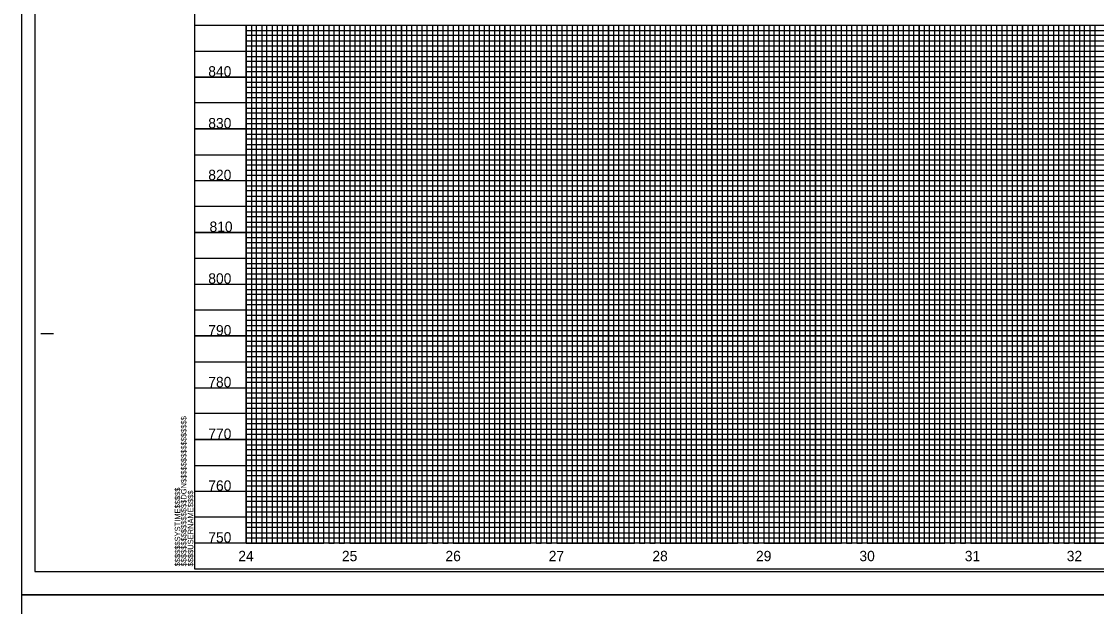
# Model space of a CAD drawing. Extents: x 1755181 to 1757273, y 729911 to 735411.
# Drawn here: x 1755181 to 1756219, y 734300 to 734864 of the extents above; entities that cross this region are included whole.
import ezdxf

# ---------------------------------------------------------------- set-up
doc = ezdxf.new("R2010")
doc.units = 0
for name, color, linetype in [('Exist Vertical Profile Horizontal Axis Label Major', 7, 'Continuous'), ('Exist Vertical Profile Vertical Axis Label', 7, 'Continuous'), ('Scratch_Level_3', 7, 'Continuous'), ('Sheet Cutting Line CELL', 7, 'Continuous'), ('Sheet DOT Grid CELL', 7, 'Continuous'), ('Sheet Plot Border Inside CELL', 7, 'Continuous'), ('Sheet Plot Border Outside CELL', 7, 'Continuous'), ('Sheet Profile CELL', 7, 'Continuous'), ('Sheet Profile Grid Major CELL', 7, 'Continuous'), ('Sheet Profile Grid Middle CELL', 7, 'Continuous'), ('Sheet Profile Grid Minor CELL', 7, 'Continuous')]:
    doc.layers.add(name, color=color, linetype=linetype)

msp = doc.modelspace()

# ---------------------------------------------------------------- linework, layer by layer
at = {"layer": 'Scratch_Level_3'}
msp.add_lwpolyline([(1755397.7, 734860.8), (1756797.7, 734860.8), (1756797.7, 734360.8), (1755397.7, 734360.8)], close=True, dxfattribs=at)
at = {"layer": 'Sheet Cutting Line CELL'}
for p, q in [((1755180.7, 735410.8), (1755180.7, 734310.8)), ((1755180.7, 734310.8), (1756864.7, 734310.8)), ((1755180.7, 734310.8), (1755180.7, 733210.8))]:
    msp.add_line(p, q, dxfattribs=at)
at = {"layer": 'Sheet DOT Grid CELL'}
for p, q in [((1755347.7, 734860.8), (1756847.6, 734860.8)), ((1755397.7, 734860.8), (1755397.7, 734360.8)), ((1755447.7, 734860.8), (1755447.7, 734360.8)), ((1755497.7, 734860.8), (1755497.7, 734360.8)), ((1755547.7, 734860.8), (1755547.7, 734360.8)), ((1755597.7, 734860.8), (1755597.7, 734360.8)), ((1755647.7, 734860.8), (1755647.7, 734360.8)), ((1755697.7, 734860.8), (1755697.7, 734360.8)), ((1755747.7, 734860.8), (1755747.7, 734360.8)), ((1755797.7, 734860.8), (1755797.7, 734360.8)), ((1755847.7, 734860.8), (1755847.7, 734360.8)), ((1755897.7, 734860.8), (1755897.7, 734360.8)), ((1755947.7, 734860.8), (1755947.7, 734360.8)), ((1755997.7, 734860.8), (1755997.7, 734360.8)), ((1756047.7, 734860.8), (1756047.7, 734360.8)), ((1756097.7, 734860.8), (1756097.7, 734360.8)), ((1756147.7, 734860.8), (1756147.7, 734360.8)), ((1756197.7, 734860.8), (1756197.7, 734360.8)), ((1755347.7, 734810.8), (1756847.6, 734810.8)), ((1755347.7, 734760.8), (1756847.6, 734760.8)), ((1755347.7, 734710.8), (1756847.6, 734710.8)), ((1755347.7, 734660.8), (1756847.6, 734660.8)), ((1755347.7, 734610.8), (1756847.6, 734610.8)), ((1755347.7, 734560.8), (1756847.6, 734560.8)), ((1755347.7, 734510.8), (1756847.6, 734510.8)), ((1755347.7, 734460.8), (1756847.6, 734460.8)), ((1755347.7, 734410.8), (1756847.6, 734410.8))]:
    msp.add_line(p, q, dxfattribs=at)
at = {"layer": 'Sheet Plot Border Inside CELL'}
msp.add_lwpolyline([(1755193.7, 734333.2), (1756860.2, 734333.2), (1756860.2, 735388.3), (1755193.7, 735388.3)], close=True, dxfattribs=at)
at = {"layer": 'Sheet Plot Border Outside CELL'}
for points in [[(1755180.7, 734310.8), (1756864.7, 734310.8), (1756864.7, 735410.8), (1755180.7, 735410.8)], [(1755180.7, 733210.8), (1756864.7, 733210.8), (1756864.7, 734310.8), (1755180.7, 734310.8)]]:
    msp.add_lwpolyline(points, close=True, dxfattribs=at)
at = {"layer": 'Sheet Profile CELL'}
for p, q in [((1755347.7, 734860.8), (1756847.7, 734860.8)), ((1755199.2, 734563.3), (1755211.7, 734563.3)), ((1756847.7, 734360.8), (1755347.7, 734360.8)), ((1755347.7, 734335.8), (1756847.7, 734335.8)), ((1755347.7, 734335.8), (1755347.7, 734335.8))]:
    msp.add_line(p, q, dxfattribs=at)
msp.add_lwpolyline([(1756847.7, 735385.8), (1755347.7, 735385.8), (1755347.7, 734335.8), (1756847.7, 734335.8)], close=True, dxfattribs=at)
msp.add_lwpolyline([(1755385.2, 734335.8), (1755385.2, 734335.8)], dxfattribs=at)
at = {"layer": 'Sheet Profile Grid Major CELL'}
for p, q in [((1755847.7, 734860.8), (1755897.7, 734860.8)), ((1755947.7, 734860.8), (1755997.7, 734860.8)), ((1756047.7, 734860.8), (1756097.7, 734860.8)), ((1756147.7, 734860.8), (1756197.7, 734860.8)), ((1755347.7, 734361.1), (1755347.7, 734361.1))]:
    msp.add_line(p, q, dxfattribs=at)
for points in [[(1755397.7, 734860.8), (1755397.7, 734360.8), (1755447.7, 734360.8), (1755447.7, 734860.8), (1755497.7, 734860.8), (1755497.7, 734360.8), (1755547.7, 734360.8), (1755547.7, 734860.8), (1755597.7, 734860.8), (1755597.7, 734360.8), (1755647.7, 734360.8), (1755647.7, 734860.8), (1755697.7, 734860.8), (1755697.7, 734360.8), (1755747.7, 734360.8), (1755747.7, 734860.8), (1755797.7, 734860.8), (1755797.7, 734360.8), (1755847.7, 734360.8), (1755847.7, 734860.8), (1755897.7, 734860.8), (1755897.7, 734360.8), (1755947.7, 734360.8), (1755947.7, 734860.8), (1755997.7, 734860.8), (1755997.7, 734360.8), (1756047.7, 734360.8), (1756047.7, 734860.8), (1756097.7, 734860.8), (1756097.7, 734360.8), (1756147.7, 734360.8), (1756147.7, 734860.8), (1756197.7, 734860.8), (1756197.7, 734360.8), (1756247.7, 734360.8)], [(1756847.7, 734810.8), (1755347.7, 734810.8)], [(1756847.7, 734760.8), (1755347.7, 734760.8), (1755347.7, 734710.8), (1756847.7, 734710.8)], [(1756847.7, 734660.8), (1755347.7, 734660.8), (1755347.7, 734610.8), (1756847.7, 734610.8)], [(1756847.7, 734560.8), (1755347.7, 734560.8), (1755347.7, 734510.8), (1756847.7, 734510.8)], [(1756847.7, 734460.8), (1755347.7, 734460.8), (1755347.7, 734460.8), (1755347.7, 734410.8), (1756847.7, 734410.8)], [(1756847.7, 734360.8), (1755347.7, 734360.8)]]:
    msp.add_lwpolyline(points, dxfattribs=at)
at = {"layer": 'Sheet Profile Grid Middle CELL'}
for points in [[(1755372.7, 734860.8), (1755422.7, 734860.8), (1755422.7, 734360.8), (1755472.7, 734360.8), (1755472.7, 734860.8), (1755522.7, 734860.8), (1755522.7, 734360.8), (1755572.7, 734360.8), (1755572.7, 734860.8), (1755622.7, 734860.8), (1755622.7, 734360.8), (1755672.7, 734360.8), (1755672.7, 734860.8), (1755722.7, 734860.8), (1755722.7, 734360.8), (1755772.7, 734360.8), (1755772.7, 734860.8), (1755822.7, 734860.8), (1755822.7, 734360.8), (1755872.7, 734360.8), (1755872.7, 734860.8), (1755922.7, 734860.8), (1755922.7, 734360.8), (1755972.7, 734360.8), (1755972.7, 734360.8), (1755972.7, 734860.8), (1756022.7, 734860.8), (1756022.7, 734360.8), (1756072.7, 734360.8), (1756072.7, 734860.8), (1756122.7, 734860.8), (1756122.7, 734360.8), (1756172.7, 734360.8), (1756172.7, 734860.8), (1756222.7, 734860.8)], [(1755347.7, 734835.8), (1756847.7, 734835.8)], [(1756847.7, 734785.8), (1755347.7, 734785.8), (1755347.7, 734735.8), (1756847.7, 734735.8)], [(1756847.7, 734685.8), (1755347.7, 734685.8), (1755347.7, 734635.8), (1756847.7, 734635.8)], [(1756847.7, 734585.8), (1755347.7, 734585.8), (1755347.7, 734535.8), (1756847.7, 734535.8)], [(1756847.7, 734485.8), (1755347.7, 734485.8), (1755347.7, 734435.8), (1756847.7, 734435.8)], [(1756847.7, 734385.8), (1755347.7, 734385.8)]]:
    msp.add_lwpolyline(points, dxfattribs=at)
at = {"layer": 'Sheet Profile Grid Minor CELL'}
for p, q in [((1755397.7, 734855.8), (1756797.7, 734855.8)), ((1756797.7, 734850.8), (1755397.7, 734850.8)), ((1755397.7, 734845.8), (1756797.7, 734845.8)), ((1756797.7, 734840.8), (1755397.7, 734840.8)), ((1755397.7, 734830.8), (1756797.7, 734830.8)), ((1756797.7, 734825.8), (1755397.7, 734825.8)), ((1755397.7, 734820.8), (1756797.7, 734820.8)), ((1756797.7, 734815.8), (1755397.7, 734815.8)), ((1755397.7, 734805.8), (1756797.7, 734805.8)), ((1756797.7, 734800.8), (1755397.7, 734800.8)), ((1755397.7, 734795.8), (1756797.7, 734795.8)), ((1756797.7, 734790.8), (1755397.7, 734790.8)), ((1755397.7, 734780.8), (1756797.7, 734780.8)), ((1756797.7, 734775.8), (1755397.7, 734775.8)), ((1755397.7, 734770.8), (1756797.7, 734770.8)), ((1756797.7, 734765.8), (1755397.7, 734765.8)), ((1755397.7, 734755.8), (1756797.7, 734755.8)), ((1756797.7, 734750.8), (1755397.7, 734750.8)), ((1755397.7, 734745.8), (1756797.7, 734745.8)), ((1756797.7, 734740.8), (1755397.7, 734740.8)), ((1755397.7, 734730.8), (1756797.7, 734730.8)), ((1756797.7, 734725.8), (1755397.7, 734725.8)), ((1755397.7, 734720.8), (1756797.7, 734720.8)), ((1756797.7, 734715.8), (1755397.7, 734715.8)), ((1755397.7, 734705.8), (1756797.7, 734705.8)), ((1756797.7, 734700.8), (1755397.7, 734700.8)), ((1755397.7, 734695.8), (1756797.7, 734695.8)), ((1756797.7, 734690.8), (1755397.7, 734690.8)), ((1755397.7, 734680.8), (1756797.7, 734680.8)), ((1756797.7, 734675.8), (1755397.7, 734675.8)), ((1755397.7, 734670.8), (1756797.7, 734670.8)), ((1756797.7, 734665.8), (1755397.7, 734665.9)), ((1755397.7, 734655.8), (1756797.7, 734655.8)), ((1756797.7, 734650.8), (1755397.7, 734650.8)), ((1755397.7, 734645.8), (1756797.7, 734645.8)), ((1756797.7, 734640.8), (1755397.7, 734640.8)), ((1755397.7, 734630.8), (1756797.7, 734630.8)), ((1756797.7, 734625.8), (1755397.7, 734625.8)), ((1755397.7, 734620.8), (1756797.7, 734620.8)), ((1756797.7, 734615.8), (1755397.7, 734615.8)), ((1755397.7, 734605.8), (1756797.7, 734605.8)), ((1756797.7, 734600.8), (1755397.7, 734600.8)), ((1755397.7, 734595.8), (1756797.7, 734595.8)), ((1756797.7, 734590.8), (1755397.7, 734590.8)), ((1755397.7, 734580.8), (1756797.7, 734580.8)), ((1756797.7, 734575.8), (1755397.7, 734575.8)), ((1755397.7, 734570.8), (1756797.7, 734570.8)), ((1756797.7, 734565.8), (1755397.7, 734565.8)), ((1755397.7, 734555.8), (1756797.7, 734555.8)), ((1756797.7, 734550.8), (1755397.7, 734550.8)), ((1755397.7, 734545.8), (1756797.7, 734545.8)), ((1756797.7, 734540.8), (1755397.7, 734540.8)), ((1755397.7, 734530.8), (1756797.7, 734530.8)), ((1756797.7, 734525.8), (1755397.7, 734525.8)), ((1755397.7, 734520.8), (1756797.7, 734520.8)), ((1756797.7, 734515.8), (1755397.7, 734515.8)), ((1755397.7, 734505.8), (1756797.7, 734505.8)), ((1756797.7, 734500.8), (1755397.7, 734500.8)), ((1755397.7, 734495.8), (1756797.7, 734495.8)), ((1756797.7, 734490.8), (1755397.7, 734490.8)), ((1755397.7, 734480.8), (1756797.7, 734480.8)), ((1756797.7, 734475.8), (1755397.7, 734475.8)), ((1755397.7, 734470.8), (1756797.7, 734470.8)), ((1756797.7, 734465.8), (1755397.7, 734465.8)), ((1755397.7, 734455.8), (1756797.7, 734455.8)), ((1756797.7, 734450.8), (1755397.7, 734450.8)), ((1755397.7, 734445.8), (1756797.7, 734445.8)), ((1756797.7, 734440.8), (1755397.7, 734440.8)), ((1755397.7, 734430.8), (1756797.7, 734430.8)), ((1756797.7, 734425.8), (1755397.7, 734425.8)), ((1755397.7, 734420.8), (1756797.7, 734420.8)), ((1756797.7, 734415.8), (1755397.7, 734415.8)), ((1755397.7, 734405.8), (1756797.7, 734405.8)), ((1756797.7, 734400.8), (1755397.7, 734400.8)), ((1755397.7, 734395.8), (1756797.7, 734395.8)), ((1756797.7, 734390.8), (1755397.7, 734390.8)), ((1755397.7, 734380.8), (1756797.7, 734380.8)), ((1756797.7, 734375.8), (1755397.7, 734375.8)), ((1755397.7, 734370.8), (1756797.7, 734370.8)), ((1755397.7, 734365.8), (1756797.7, 734365.8))]:
    msp.add_line(p, q, dxfattribs=at)
for points in [[(1755397.7, 734860.8), (1755402.7, 734860.8), (1755402.7, 734360.8), (1755407.7, 734360.8), (1755407.7, 734860.8), (1755412.7, 734860.8), (1755412.7, 734360.8), (1755417.7, 734360.8), (1755417.7, 734860.8), (1755427.7, 734860.8), (1755427.7, 734360.8), (1755432.7, 734360.8), (1755432.7, 734860.8), (1755437.7, 734860.8), (1755437.7, 734360.8), (1755442.7, 734360.8), (1755452.7, 734360.8), (1755457.7, 734360.8), (1755457.7, 734860.8), (1755462.7, 734860.8), (1755462.7, 734360.8), (1755467.7, 734360.8), (1755467.7, 734860.8), (1755477.7, 734860.8), (1755477.7, 734360.8), (1755482.7, 734360.8), (1755482.7, 734860.8), (1755487.7, 734860.8), (1755487.7, 734360.8), (1755492.7, 734360.8), (1755492.7, 734860.8), (1755502.7, 734860.8), (1755502.7, 734360.8), (1755507.7, 734360.8), (1755507.7, 734860.8), (1755512.7, 734860.8), (1755512.7, 734360.8), (1755517.7, 734360.8), (1755517.7, 734860.8), (1755527.7, 734860.8), (1755527.7, 734360.8), (1755532.7, 734360.8), (1755532.7, 734860.8), (1755537.7, 734860.8), (1755537.7, 734360.8), (1755542.7, 734360.8), (1755542.7, 734860.8), (1755552.7, 734860.8), (1755552.7, 734360.8), (1755557.7, 734360.8), (1755557.7, 734860.8), (1755562.7, 734860.8), (1755562.7, 734360.8), (1755567.7, 734360.8), (1755567.7, 734860.8), (1755577.7, 734860.8), (1755577.7, 734360.8), (1755582.7, 734360.8), (1755582.7, 734860.8), (1755587.7, 734860.8), (1755587.7, 734360.8), (1755592.7, 734360.8), (1755592.7, 734860.8), (1755602.7, 734860.8), (1755602.7, 734360.8), (1755607.7, 734360.8), (1755607.7, 734860.8), (1755612.7, 734860.8), (1755612.7, 734360.8)], [(1755442.7, 734360.8), (1755442.7, 734860.8), (1755452.7, 734860.8), (1755452.7, 734360.8)], [(1755612.7, 734360.8), (1755617.7, 734360.8), (1755617.7, 734860.8), (1755627.7, 734860.8), (1755627.7, 734360.8), (1755632.7, 734360.8), (1755632.7, 734860.8), (1755637.7, 734860.8), (1755637.7, 734360.8), (1755642.7, 734360.8), (1755642.7, 734860.8), (1755652.7, 734860.8), (1755652.7, 734360.8), (1755657.7, 734360.8), (1755657.7, 734860.8), (1755662.7, 734860.8), (1755662.7, 734360.8), (1755667.7, 734360.8), (1755667.7, 734860.8), (1755677.7, 734860.8), (1755677.7, 734360.8), (1755682.7, 734360.8), (1755682.7, 734860.8), (1755687.7, 734860.8), (1755687.7, 734360.8), (1755692.7, 734360.8), (1755692.7, 734860.8), (1755702.7, 734860.8), (1755702.7, 734360.8), (1755707.7, 734360.8), (1755707.7, 734860.8), (1755712.7, 734860.8), (1755712.7, 734360.8), (1755717.7, 734360.8), (1755717.7, 734860.8), (1755727.7, 734860.8), (1755727.7, 734360.8), (1755732.7, 734360.8), (1755732.7, 734860.8), (1755737.7, 734860.8), (1755737.7, 734360.8), (1755742.7, 734360.8), (1755742.7, 734860.8), (1755752.7, 734860.8), (1755752.7, 734360.8), (1755757.7, 734360.8), (1755757.7, 734860.8), (1755762.7, 734860.8), (1755762.7, 734360.8), (1755767.7, 734360.8), (1755767.7, 734860.8), (1755777.7, 734860.8), (1755777.7, 734360.8), (1755782.7, 734360.8), (1755782.7, 734860.8), (1755787.7, 734860.8), (1755787.7, 734360.8), (1755792.7, 734360.8), (1755792.7, 734860.8), (1755802.7, 734860.8), (1755802.7, 734360.8), (1755807.7, 734360.8), (1755807.7, 734860.8), (1755812.7, 734860.8), (1755812.7, 734360.8), (1755817.7, 734360.8), (1755817.7, 734860.8), (1755827.7, 734860.8), (1755827.7, 734360.8), (1755832.7, 734360.8), (1755832.7, 734860.8), (1755837.7, 734860.8), (1755837.7, 734360.8), (1755842.7, 734360.8), (1755842.7, 734860.8), (1755852.7, 734860.8), (1755852.7, 734360.8), (1755857.7, 734360.8), (1755857.7, 734860.8), (1755862.7, 734860.8), (1755862.7, 734360.8), (1755867.7, 734360.8), (1755867.7, 734860.8), (1755877.7, 734860.8), (1755877.7, 734360.8), (1755882.7, 734360.8), (1755882.7, 734860.8), (1755887.7, 734860.8), (1755887.7, 734360.8), (1755892.7, 734360.8), (1755892.7, 734860.8), (1755902.7, 734860.8), (1755902.7, 734360.8), (1755907.7, 734360.8), (1755907.7, 734860.8), (1755912.7, 734860.8), (1755912.7, 734360.8), (1755917.7, 734360.8), (1755917.7, 734860.8), (1755927.7, 734860.8)], [(1755927.7, 734860.8), (1755927.7, 734360.8), (1755932.7, 734360.8), (1755932.7, 734860.8), (1755937.7, 734860.8), (1755937.7, 734360.8), (1755942.7, 734360.8), (1755942.7, 734860.8), (1755952.7, 734860.8), (1755952.7, 734360.8), (1755957.7, 734360.8), (1755957.7, 734860.8), (1755962.7, 734860.8), (1755962.7, 734360.8), (1755967.7, 734360.8), (1755967.7, 734860.8), (1755977.7, 734860.8), (1755977.7, 734360.8), (1755982.7, 734360.8), (1755982.7, 734860.8), (1755987.7, 734860.8), (1755987.7, 734360.8), (1755992.7, 734360.8), (1755992.7, 734860.8), (1756002.7, 734860.8), (1756002.7, 734360.8), (1756007.7, 734360.8), (1756007.7, 734860.8), (1756012.7, 734860.8), (1756012.7, 734360.8), (1756017.7, 734360.8), (1756017.7, 734860.8), (1756027.7, 734860.8), (1756027.7, 734360.8), (1756032.7, 734360.8), (1756032.7, 734860.8), (1756037.7, 734860.8), (1756037.7, 734360.8), (1756042.7, 734360.8), (1756042.7, 734860.8), (1756052.7, 734860.8), (1756052.7, 734360.8), (1756052.7, 734360.8), (1756057.7, 734360.8), (1756057.7, 734860.8), (1756062.7, 734860.8), (1756062.7, 734360.8), (1756067.7, 734360.8), (1756067.7, 734860.8), (1756077.7, 734860.8), (1756077.7, 734360.8), (1756082.7, 734360.8), (1756082.7, 734860.8), (1756087.7, 734860.8), (1756087.7, 734360.8), (1756092.7, 734360.8), (1756092.7, 734860.8), (1756102.7, 734860.8), (1756102.7, 734360.8), (1756107.7, 734360.8), (1756107.7, 734860.8), (1756112.7, 734860.8), (1756112.7, 734360.8), (1756117.7, 734360.8), (1756117.7, 734860.8), (1756127.7, 734860.8), (1756127.7, 734360.8), (1756132.7, 734360.8), (1756132.7, 734860.8), (1756137.7, 734860.8), (1756137.7, 734360.8), (1756142.7, 734360.8), (1756142.7, 734860.8), (1756152.7, 734860.8), (1756152.7, 734360.8), (1756157.7, 734360.8), (1756157.7, 734860.8), (1756162.7, 734860.8), (1756162.7, 734360.8), (1756167.7, 734360.8), (1756167.7, 734860.8), (1756177.7, 734860.8), (1756177.7, 734360.8), (1756182.7, 734360.8), (1756182.7, 734860.8), (1756187.7, 734860.8), (1756187.7, 734360.8), (1756192.7, 734360.8), (1756192.7, 734860.8), (1756202.7, 734860.8), (1756202.7, 734360.8), (1756207.4, 734361.3), (1756207.7, 734360.8), (1756207.7, 734860.8), (1756212.7, 734860.8), (1756212.7, 734360.8), (1756217.7, 734360.8), (1756217.7, 734860.8), (1756227.7, 734860.8)]]:
    msp.add_lwpolyline(points, dxfattribs=at)

# ---------------------------------------------------------------- texts
at = {"layer": 'Exist Vertical Profile Horizontal Axis Label Major'}
for s, p in [('24', (1755390.1, 734343.3)), ('25', (1755490.2, 734343.3)), ('26', (1755590.2, 734343.3)), ('27', (1755690, 734343.3)), ('28', (1755790.1, 734343.3)), ('29', (1755890.2, 734343.3)), ('30', (1755990.1, 734343.3)), ('31', (1756091.9, 734343.3)), ('32', (1756190.4, 734343.3))]:
    msp.add_text(s, height=10, dxfattribs=at).set_placement(p)
at = {"layer": 'Exist Vertical Profile Vertical Axis Label'}
for s, p in [('840', (1755361.1, 734811.3)), ('830', (1755361.1, 734761.3)), ('820', (1755361.1, 734711.3)), ('810', (1755362.3, 734661.3)), ('800', (1755361.1, 734611.3)), ('790', (1755361.1, 734561.3)), ('780', (1755361.1, 734511.3)), ('770', (1755361.1, 734461.3)), ('760', (1755361.1, 734411.3)), ('750', (1755361.1, 734361.3))]:
    msp.add_text(s, height=10, dxfattribs=at).set_placement(p)
at = {"layer": 'Sheet Profile CELL'}
for s, p in [('$$$$$$$$$$$$$$$$DGN$$$$$$$$$$$$$$$$', (1755340, 734338.2)), ('$$$$$$SYSTIME$$$$$', (1755334, 734338.2)), ('$$$$USERNAME$$$$', (1755346.6, 734338.2))]:
    msp.add_text(s, height=5.25, rotation=90, dxfattribs=at).set_placement(p)

doc.saveas('drawing.dxf')
